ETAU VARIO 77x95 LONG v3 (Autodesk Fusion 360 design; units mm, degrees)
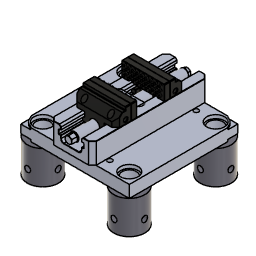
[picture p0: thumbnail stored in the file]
parameter "Ouverture" = 50
base_feature "Base Feature1"
joint_origin "JointOrigin1" OffsetX 0 OffsetY 0 OffsetZ 0
base_feature "Base Feature1"
base_feature "Base Feature1"
base_feature "Base Feature1"
joint_origin "JointOrigin1" OffsetX 0 OffsetY 0 OffsetZ 0
base_feature "Base Feature1"
base_feature "Base Feature1"
base_feature "Base Feature1"
base_feature "Base Feature1"
base_feature "Base Feature1"
base_feature "Base Feature1"
as_built_joint "As-built1"
ground "Ground1"
as_built_joint "As-built1"
as_built_joint "As-built1"
as_built_joint "As-built2"
joint "Assemble1" alignOffsetX 0 alignOffsetY 0 alignOffsetZ 25 (= "Ouverture / 2")
joint "Assemble2" alignOffsetX 0 alignOffsetY 0 alignOffsetZ 25 (= "Ouverture / 2")
position "Position1"
base_feature "Fonction de base"
position "Position2"
rectangular_pattern "00000000-0000-0000-0000-000000000000" uSpaceDistance -156 vSpaceDistance 156
position "Position3" TranslateAlongZ 0
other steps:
create_component "CreateComponent1"
create_component "CreateComponent1"
create_component "CreateComponent2"
create_component "CreateComponent2"
create_component "CreateComponent1"
create_component "CreateComponent2"
create_component "CreateComponent3"
create_component "CreateComponent1"
create_component "CreateComponent2"
create_component "CreateComponent3"
create_component "CreateComponent4"
joint_origin "JointOrigin1" OffsetX 0 OffsetY 0 OffsetZ 0
joint_origin "JointOrigin2" OffsetX 0 OffsetY 0 OffsetZ 0
create_component "CreateComponent4"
